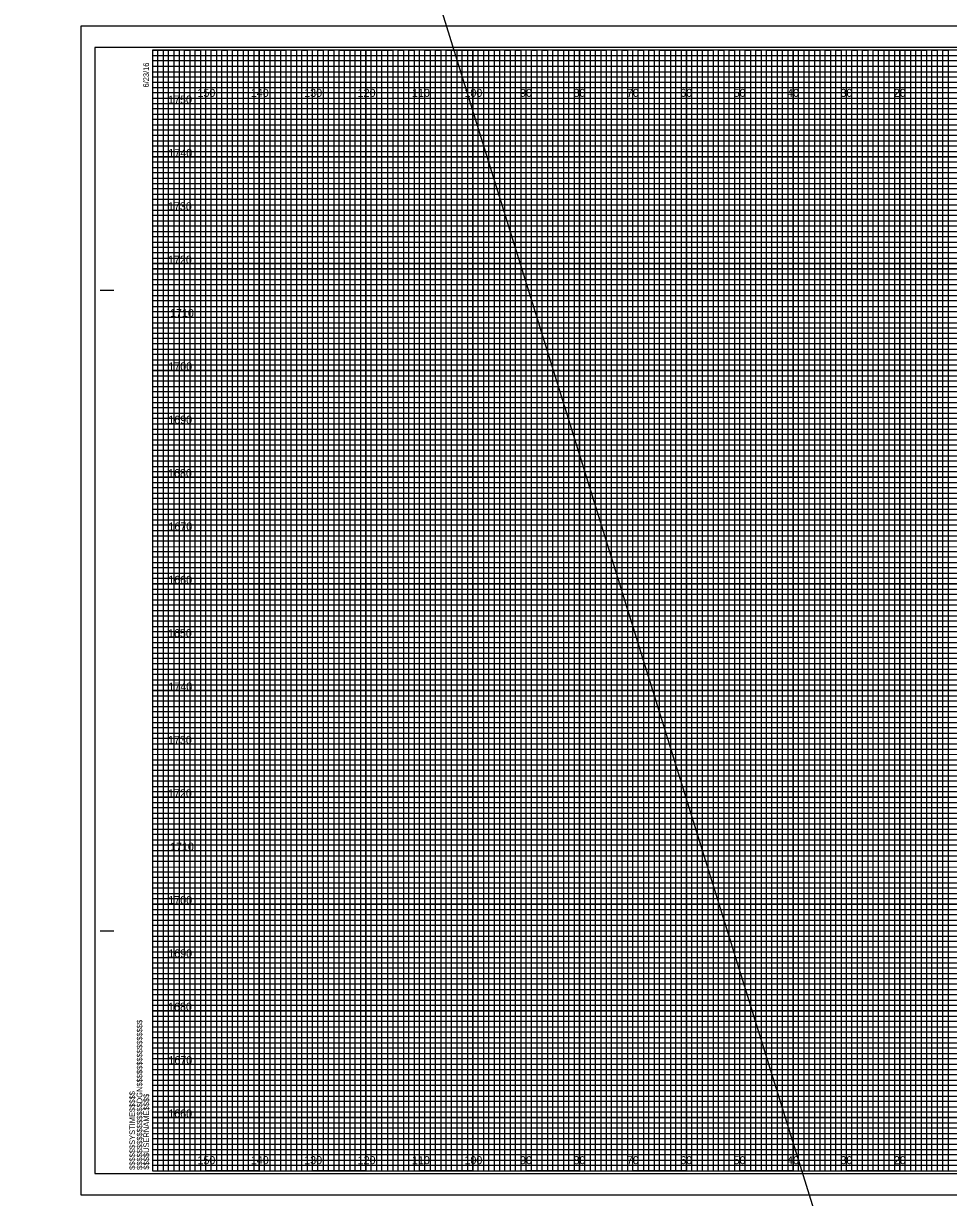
# Model space of a CAD drawing. Extents: x -419 to 4739, y -630 to 13534.
# Drawn here: x 1187.1 to 1360.3, y 859.1 to 1079.1 of the extents above; entities that cross this region are included whole.
import ezdxf

# ---------------------------------------------------------------- set-up
doc = ezdxf.new("R2010")
doc.units = 0
for name, color, linetype in [('Old_Level_62', 7, 'Continuous'), ('Pattern 1', 7, 'Continuous'), ('Pattern 18', 7, 'Continuous'), ('Pattern 4', 7, 'Continuous'), ('Pattern 5', 7, 'Continuous'), ('Prop Dimension', 7, 'Continuous'), ('Prop Horizontal Alignment', 7, 'Continuous'), ('Raster_Level_0', 7, 'Continuous'), ('Scratch_Level_0', 7, 'Continuous'), ('Scratch_Level_3', 7, 'Continuous'), ('Scratch_Level_5', 7, 'Continuous')]:
    doc.layers.add(name, color=color, linetype=linetype)

msp = doc.modelspace()

# ---------------------------------------------------------------- linework, layer by layer
at = {"layer": 'Old_Level_62'}
for p, q in [((1201.42, 1029.06), (1203.92, 1029.06)), ((1201.52, 1029.06), (1204.02, 1029.06)), ((1201.42, 909.06), (1203.92, 909.06)), ((1201.52, 909.06), (1204.02, 909.06)), ((1211.22, 864.06), (1211.22, 864.06)), ((1211.22, 864.06), (1211.22, 864.06)), ((1211.22, 864.06), (1211.22, 864.06)), ((1211.22, 864.06), (1211.22, 864.06)), ((1211.22, 864.06), (1211.22, 864.06)), ((1211.22, 864.06), (1211.22, 864.06)), ((1211.22, 864.06), (1211.22, 864.06))]:
    msp.add_line(p, q, dxfattribs=at)
msp.add_lwpolyline([(1531.22, 1074.06), (1211.22, 1074.06), (1211.22, 864.06), (1531.22, 864.06)], close=True, dxfattribs=at)
at = {"layer": 'Pattern 18'}
msp.add_line((-76.07, 5407.18), (1796.19, -630.13), dxfattribs=at)
msp.add_lwpolyline([(1197.82, 859.56), (1534.52, 859.56), (1534.52, 1078.56), (1197.82, 1078.56)], close=True, dxfattribs=at)
at = {"layer": 'Pattern 4'}
for p, q in [((1211.22, 1073.06), (1471.22, 1073.06)), ((1471.22, 1072.04), (1211.22, 1072.04)), ((1211.22, 1072.04), (1211.22, 1071.06)), ((1211.22, 1071.06), (1471.22, 1071.06)), ((1471.22, 1069.95), (1211.22, 1069.95)), ((1211.22, 1069.95), (1211.22, 1068.06)), ((1211.22, 1068.06), (1531.22, 1068.06))]:
    msp.add_line(p, q, dxfattribs=at)
for points in [[(1211.22, 1067.06), (1481.22, 1067.06), (1531.22, 1067.06), (1531.22, 1066.06), (1211.22, 1066.06)], [(1211.22, 1065.06), (1531.22, 1065.06), (1531.22, 1063.06), (1211.22, 1063.06)], [(1211.22, 1062.06), (1531.22, 1062.06), (1531.22, 1061.06), (1211.22, 1061.04)], [(1211.22, 1060.06), (1531.22, 1060.06), (1531.22, 1058.06), (1211.22, 1058.06)], [(1211.22, 1057.06), (1531.22, 1057.06), (1531.22, 1056.06), (1211.22, 1056.06)], [(1211.22, 1055.06), (1531.22, 1055.06), (1531.22, 1053.06), (1211.22, 1053.06)], [(1211.22, 1052.06), (1531.22, 1052.06), (1531.22, 1051.06), (1211.22, 1051.06)], [(1211.22, 1050.06), (1531.22, 1050.06), (1531.22, 1048.06), (1211.22, 1048.06)], [(1211.22, 1047.06), (1531.22, 1047.06), (1531.22, 1046.06), (1211.22, 1046.06)], [(1211.22, 1045.06), (1531.22, 1045.06), (1531.22, 1043.06), (1211.22, 1043.06)], [(1211.22, 1042.06), (1531.22, 1042.06), (1531.22, 1041.06), (1211.22, 1041.06)], [(1211.22, 1040.06), (1531.22, 1040.06), (1531.22, 1038.01), (1531.22, 1037.06), (1531.22, 1036.06), (1211.22, 1036.06)], [(1211.22, 1038.06), (1531.22, 1038.06), (1531.22, 1037.06), (1211.22, 1037.06)], [(1211.22, 1035.06), (1531.22, 1035.06), (1531.22, 1033.06), (1211.22, 1033.09)], [(1211.22, 1033.09), (1531.22, 1033.06), (1531.22, 1032.06), (1211.22, 1032.06)], [(1211.22, 1031.06), (1531.22, 1031.06), (1531.22, 1030.06), (1211.22, 1030.06)], [(1211.22, 1028.06), (1531.22, 1028.06), (1531.22, 1027.06), (1211.22, 1027.06)], [(1211.22, 1026.06), (1531.22, 1026.06), (1531.22, 1025.06), (1211.22, 1025.06)], [(1211.15, 1022.95), (1531.22, 1022.95), (1531.22, 1021.94), (1211.15, 1021.94)], [(1211.22, 1021.06), (1531.22, 1021.06), (1531.22, 1020.06), (1211.22, 1020.06)], [(1211.22, 1018.06), (1531.22, 1018.06), (1531.22, 1017.06), (1211.22, 1017.06)], [(1211.22, 1016.06), (1531.22, 1016.06), (1531.22, 1015.06), (1211.22, 1015.06)], [(1211.22, 1013.06), (1531.22, 1013.06), (1531.22, 1012.06), (1211.22, 1012.06)], [(1211.22, 1011.06), (1531.22, 1011.06), (1531.22, 1010.06), (1211.22, 1010.06)], [(1211.22, 1008.06), (1531.22, 1008.06), (1531.22, 1007.06), (1211.22, 1007.06)], [(1211.22, 1006.06), (1531.22, 1006.06), (1531.22, 1005.06), (1211.22, 1005.06)], [(1211.22, 1003.06), (1531.22, 1003.06), (1531.21, 1002.04), (1211.22, 1002.06)], [(1211.22, 1001.06), (1531.22, 1001.06), (1531.22, 1000.06), (1211.22, 1000.06)], [(1211.22, 998.06), (1531.22, 998.06), (1531.22, 997.06), (1211.22, 997.06)], [(1211.22, 996.06), (1531.22, 996.06), (1531.22, 995.06), (1211.22, 995.06)], [(1211.22, 993.06), (1531.22, 993.06), (1531.22, 992.06), (1211.22, 992.06)], [(1211.22, 991.06), (1531.22, 991.06), (1531.22, 990.06), (1211.22, 990.06)], [(1211.22, 988.06), (1531.22, 988.06), (1531.22, 987.06), (1211.22, 987.06)], [(1211.22, 986.06), (1531.22, 986.06), (1531.22, 985.06), (1211.22, 985.06)], [(1211.22, 983.06), (1531.22, 983.06), (1531.22, 982.06), (1211.22, 982.06)], [(1211.22, 981.05), (1531.29, 980.97), (1531.22, 980.06), (1211.22, 980.06)], [(1211.22, 978.06), (1531.22, 978.06), (1531.22, 977.06), (1211.22, 977.06)], [(1211.22, 976.06), (1531.22, 976.06), (1531.22, 975.06), (1211.22, 975.06)], [(1211.22, 973.06), (1531.22, 973.06), (1531.22, 972.06), (1211.22, 972.06)], [(1211.22, 971.06), (1531.22, 971.06), (1531.22, 970.06), (1211.22, 970.06)], [(1211.22, 968.06), (1531.22, 968.06), (1531.22, 967.06), (1211.22, 967.06)], [(1211.22, 966.06), (1531.22, 966.06), (1531.22, 965.06), (1211.22, 965.06)], [(1211.22, 963.06), (1531.22, 963.06), (1531.22, 962.06), (1211.22, 962.06)], [(1211.22, 961.06), (1531.22, 961.06), (1531.22, 960.06), (1211.22, 960.06)], [(1211.22, 958.06), (1531.22, 958.06), (1531.22, 957.06), (1211.22, 957.06)], [(1211.22, 956.06), (1531.22, 956.06), (1531.22, 955.06), (1211.22, 955.06)], [(1211.22, 953.06), (1531.22, 953.06), (1531.22, 952.06), (1211.22, 952.06)], [(1211.22, 951.06), (1531.22, 951.06), (1531.22, 950.06), (1211.22, 950.06)], [(1211.22, 948.06), (1531.22, 948.06), (1531.22, 947.06), (1211.22, 947.06)], [(1211.22, 946.06), (1531.22, 946.06), (1531.22, 945.06), (1211.22, 945.06)], [(1211.22, 943.06), (1531.22, 943.06), (1531.21, 942.04), (1211.22, 942.06)], [(1211.22, 941.06), (1531.22, 941.06), (1531.22, 940.06), (1211.22, 940.06)], [(1211.22, 938.06), (1531.22, 938.06), (1531.22, 937.06), (1211.22, 937.06)], [(1211.22, 936.06), (1531.22, 936.06), (1531.22, 935.06), (1211.22, 935.06)], [(1211.22, 933.06), (1531.22, 933.06), (1531.22, 932.06), (1211.22, 932.06)], [(1211.22, 931.06), (1531.22, 931.06), (1531.22, 930.06), (1211.22, 930.06)], [(1211.22, 928.06), (1531.22, 928.06), (1531.22, 927.06), (1211.22, 927.06)], [(1211.22, 926.06), (1531.22, 926.06), (1531.22, 925.06), (1211.22, 925.06)], [(1211.22, 923.06), (1531.22, 923.06), (1531.22, 922.06), (1211.22, 922.06)], [(1211.22, 921.05), (1531.29, 920.97), (1531.22, 920.06), (1211.22, 920.06)], [(1211.22, 918.06), (1531.22, 918.06), (1531.22, 917.06), (1211.22, 917.06)], [(1211.22, 916.06), (1531.22, 916.06), (1531.22, 915.06), (1211.22, 915.06)], [(1211.22, 913.06), (1531.22, 913.06), (1531.22, 912.06), (1211.22, 912.06)], [(1211.22, 911.06), (1531.22, 911.06), (1531.22, 910.06), (1211.22, 910.06)], [(1211.22, 908.06), (1531.22, 908.06), (1531.22, 907.06), (1211.22, 907.06)], [(1211.22, 906.06), (1531.22, 906.06), (1531.22, 905.06), (1211.22, 905.06)], [(1211.22, 903.06), (1531.22, 903.06), (1531.22, 902.06), (1211.22, 902.06)], [(1211.22, 901.06), (1531.22, 901.06), (1531.22, 900.06), (1211.22, 900.06)], [(1211.22, 898.06), (1531.22, 898.06), (1531.22, 897.06), (1211.22, 897.06)], [(1211.22, 896.06), (1531.22, 896.06), (1531.22, 895.06), (1211.22, 895.06)], [(1211.22, 893.06), (1531.22, 893.06), (1531.22, 892.06), (1211.22, 892.06)], [(1211.22, 891.06), (1531.22, 891.06), (1531.22, 890.06), (1211.22, 890.06)], [(1211.22, 888.06), (1531.22, 888.06), (1531.22, 887.06), (1211.22, 887.06)], [(1211.22, 886.06), (1531.22, 886.06), (1531.22, 885.06), (1211.22, 885.06)], [(1211.22, 883.06), (1531.22, 883.06), (1531.22, 882.06), (1211.22, 882.06)], [(1211.22, 881.06), (1531.22, 881.06), (1531.22, 880.06), (1211.22, 880.06)], [(1211.22, 878.06), (1531.22, 878.06), (1531.22, 877.06), (1211.22, 877.06)], [(1211.22, 876.06), (1531.22, 876.06), (1531.22, 875.06), (1211.22, 875.06)], [(1211.22, 873.06), (1531.22, 873.06), (1531.22, 872.06), (1211.22, 872.06)], [(1211.22, 871.06), (1531.22, 871.06), (1531.22, 870.06), (1211.22, 870.06)], [(1211.22, 868.06), (1531.22, 868.06), (1531.22, 867.06), (1211.22, 867.06)], [(1211.22, 866.06), (1531.22, 866.06), (1531.22, 865.06), (1211.22, 865.06)]]:
    msp.add_lwpolyline(points, dxfattribs=at)
at = {"layer": 'Pattern 5'}
for p, q in [((1534.52, 1078.56), (1197.82, 1078.56)), ((1197.82, 1078.56), (1197.82, 859.56)), ((1197.82, 859.56), (1534.52, 859.56))]:
    msp.add_line(p, q, dxfattribs=at)
at = {"layer": 'Prop Dimension'}
for points in [[(1211.22, 864.06), (1212.22, 864.06), (1212.22, 1074.06), (1213.22, 1074.06), (1213.22, 864.06)], [(1213.22, 864.06), (1214.22, 864.06), (1214.22, 1074.06), (1215.22, 1074.06), (1215.22, 864.06)], [(1216.22, 864.06), (1217.22, 864.06), (1217.22, 1074.06), (1218.22, 1074.06), (1218.22, 864.06)], [(1218.22, 864.06), (1219.22, 864.06), (1219.22, 1074.06), (1220.22, 1074.06), (1220.22, 864.06)], [(1221.22, 864.06), (1222.22, 864.06), (1222.22, 1074.06), (1223.22, 1074.06), (1223.22, 864.06)], [(1223.22, 864.06), (1224.22, 864.06), (1224.22, 1074.06), (1225.22, 1074.06), (1225.22, 864.06)], [(1226.22, 864.06), (1227.22, 864.06), (1227.22, 1074.06), (1228.22, 1074.06), (1228.22, 864.06)], [(1228.22, 864.06), (1229.22, 864.06), (1229.22, 1074.06), (1230.22, 1074.06), (1230.22, 864.06)], [(1231.22, 864.06), (1232.22, 864.06), (1232.22, 1074.06), (1233.22, 1074.06), (1233.22, 864.06)], [(1233.22, 864.06), (1234.22, 864.06), (1234.22, 1074.06), (1235.22, 1074.06), (1235.22, 864.06)], [(1236.22, 864.06), (1237.22, 864.06), (1237.22, 1074.06), (1238.22, 1074.06), (1238.22, 864.06)], [(1238.22, 864.06), (1239.22, 864.06), (1239.22, 1074.06), (1240.22, 1074.06), (1240.22, 864.06)], [(1241.22, 864.06), (1242.22, 864.06), (1242.22, 1074.06), (1243.22, 1074.06), (1243.22, 864.06)], [(1243.22, 864.06), (1244.22, 864.06), (1244.22, 1074.06), (1245.22, 1074.06), (1245.22, 864.06)], [(1246.22, 864.06), (1247.22, 864.06), (1247.22, 1074.06), (1248.22, 1074.06), (1248.22, 864.06)], [(1248.22, 864.06), (1249.22, 864.06), (1249.22, 1074.06), (1250.22, 1074.06), (1250.22, 864.06)], [(1251.22, 864.06), (1252.22, 864.06), (1252.22, 1074.06), (1253.22, 1074.06), (1253.22, 864.06)], [(1253.22, 864.06), (1254.22, 864.06), (1254.22, 1074.06), (1255.22, 1074.06), (1255.22, 864.06)], [(1256.22, 864.06), (1257.22, 864.06), (1257.22, 1074.06), (1258.22, 1074.06), (1258.22, 864.06)], [(1258.22, 864.06), (1259.22, 864.06), (1259.22, 1074.06), (1260.22, 1074.06), (1260.22, 864.06)], [(1261.22, 864.06), (1262.22, 864.06), (1262.22, 1074.06), (1263.22, 1074.06), (1263.22, 864.06)], [(1263.22, 864.06), (1264.22, 864.06), (1264.22, 1074.06), (1265.22, 1074.06), (1265.22, 864.06)], [(1266.22, 864.06), (1267.22, 864.06), (1267.22, 1074.06), (1268.22, 1074.06), (1268.22, 864.06)], [(1268.22, 864.06), (1269.22, 864.06), (1269.22, 1074.06), (1270.22, 1074.06), (1270.22, 864.06)], [(1271.22, 864.06), (1272.22, 864.06), (1272.22, 1074.06), (1273.22, 1074.06), (1273.22, 864.06)], [(1273.22, 864.06), (1274.22, 864.06), (1274.22, 1074.06), (1275.22, 1074.06), (1275.22, 864.06)], [(1276.22, 864.06), (1277.22, 864.06), (1277.22, 1074.06), (1278.22, 1074.06), (1278.22, 864.06)], [(1278.22, 864.06), (1279.22, 864.06), (1279.22, 1074.06), (1280.22, 1074.06), (1280.22, 864.06)], [(1281.22, 864.06), (1282.22, 864.06), (1282.22, 1074.06), (1283.22, 1074.06), (1283.22, 864.06)], [(1283.22, 864.06), (1284.22, 864.06), (1284.22, 1074.06), (1285.22, 1074.06), (1285.22, 864.06)], [(1286.22, 864.06), (1287.22, 864.06), (1287.22, 1074.06), (1288.22, 1074.06), (1288.22, 864.06)], [(1288.22, 864.06), (1289.22, 864.06), (1289.22, 1074.06), (1290.22, 1074.06), (1290.22, 864.06)], [(1291.22, 864.06), (1292.22, 864.06), (1292.22, 1074.06), (1293.22, 1074.06), (1293.22, 864.06)], [(1293.22, 864.06), (1294.22, 864.06), (1294.22, 1074.06), (1295.22, 1074.06), (1295.22, 864.06)], [(1296.22, 864.06), (1297.22, 864.06), (1297.22, 1074.06), (1298.22, 1074.06), (1298.22, 864.06)], [(1298.22, 864.06), (1299.22, 864.06), (1299.22, 1074.06), (1300.22, 1074.06), (1300.22, 864.06)], [(1301.22, 864.06), (1302.22, 864.06), (1302.22, 1074.06), (1303.22, 1074.06), (1303.22, 864.06)], [(1303.22, 864.06), (1304.22, 864.06), (1304.22, 1074.06), (1305.22, 1074.06), (1305.22, 864.06)], [(1306.22, 864.06), (1307.22, 864.06), (1307.22, 1074.06), (1308.22, 1074.06), (1308.22, 864.06)], [(1308.22, 864.06), (1309.22, 864.06), (1309.22, 1074.06), (1310.22, 1074.06), (1310.22, 864.06)], [(1311.22, 864.06), (1312.22, 864.06), (1312.22, 1074.06), (1313.22, 1074.06), (1313.22, 864.06)], [(1313.22, 864.06), (1314.22, 864.06), (1314.22, 1074.06), (1315.22, 1074.06), (1315.22, 864.06)], [(1316.22, 864.06), (1317.22, 864.06), (1317.22, 1074.06), (1318.22, 1074.06), (1318.22, 864.06)], [(1318.22, 864.06), (1319.22, 864.06), (1319.22, 1074.06), (1320.22, 1074.06), (1320.22, 864.06)], [(1321.22, 864.06), (1322.22, 864.06), (1322.22, 1074.06), (1323.22, 1074.06), (1323.22, 864.06)], [(1323.22, 864.06), (1324.22, 864.06), (1324.22, 1074.06), (1325.22, 1074.06), (1325.22, 864.06)], [(1326.22, 864.06), (1327.22, 864.06), (1327.22, 1074.06), (1328.22, 1074.06), (1328.22, 864.06)], [(1328.22, 864.06), (1329.22, 864.06), (1329.22, 1074.06), (1330.22, 1074.06), (1330.22, 864.06)], [(1331.22, 864.06), (1332.22, 864.06), (1332.22, 1074.06), (1333.22, 1074.06), (1333.22, 864.06)], [(1333.22, 864.06), (1334.22, 864.06), (1334.22, 1074.06), (1335.22, 1074.06), (1335.22, 864.06)], [(1336.22, 864.06), (1337.22, 864.06), (1337.22, 1074.06), (1338.22, 1074.06), (1338.22, 864.06)], [(1338.22, 864.06), (1339.22, 864.06), (1339.22, 1074.06), (1340.22, 1074.06), (1340.22, 864.06)], [(1341.22, 864.06), (1342.22, 864.06), (1342.22, 1074.06), (1343.22, 1074.06), (1343.22, 864.06)], [(1343.22, 864.06), (1344.22, 864.06), (1344.22, 1074.06), (1345.22, 1074.06), (1345.22, 864.06)], [(1346.22, 864.06), (1347.22, 864.06), (1347.22, 1074.06), (1348.22, 1074.06), (1348.22, 864.06)], [(1348.22, 864.06), (1349.22, 864.06), (1349.22, 1074.06), (1350.22, 1074.06), (1350.22, 864.06)], [(1351.22, 864.06), (1352.22, 864.06), (1352.22, 1074.06), (1353.22, 1074.06), (1353.22, 864.06)], [(1353.22, 864.06), (1354.22, 864.06), (1354.22, 1074.06), (1355.22, 1074.06), (1355.22, 864.06)], [(1356.22, 864.06), (1357.22, 864.06), (1357.22, 1074.06), (1358.22, 1074.06), (1358.22, 864.06)], [(1358.22, 864.06), (1359.22, 864.06), (1359.22, 1074.06), (1360.22, 1074.06), (1360.22, 864.06)]]:
    msp.add_lwpolyline(points, dxfattribs=at)
at = {"layer": 'Prop Horizontal Alignment'}
for points in [[(1211.22, 1074.06), (1216.22, 1074.06), (1216.22, 864.06), (1226.22, 864.06), (1226.22, 1074.06), (1236.22, 1074.06), (1236.22, 864.06), (1246.22, 864.06), (1246.22, 1074.06), (1256.22, 1074.06), (1256.22, 864.06), (1266.22, 864.06), (1266.22, 1074.06), (1276.22, 1074.06), (1276.22, 864.06), (1286.22, 864.06), (1286.22, 1074.06), (1296.22, 1074.06), (1296.22, 864.06), (1306.22, 864.06), (1306.22, 1074.06), (1316.22, 1074.06), (1316.22, 864.06), (1326.22, 864.06), (1326.22, 1074.06), (1336.22, 1074.06), (1336.22, 864.06), (1346.22, 864.06), (1346.22, 1074.06), (1356.22, 1074.06), (1356.22, 864.06), (1366.22, 864.06)], [(1211.22, 1069.06), (1486.22, 1069.06)], [(1211.22, 1049.06), (1531.22, 1049.06), (1531.22, 1059.06), (1211.22, 1059.06)], [(1211.22, 1029.06), (1531.22, 1029.06), (1531.22, 1039.06), (1211.22, 1039.06)], [(1211.22, 1009.06), (1531.22, 1009.06), (1531.22, 1019.06), (1211.22, 1019.06)], [(1211.22, 989.06), (1531.22, 989.06), (1531.22, 999.06), (1211.22, 999.06)], [(1211.22, 969.06), (1531.22, 969.06), (1531.22, 979.06), (1211.22, 979.06)], [(1211.22, 949.06), (1531.22, 949.06), (1531.22, 959.06), (1211.22, 959.06)], [(1211.22, 929.06), (1531.22, 929.06), (1531.22, 939.06), (1211.22, 939.06)], [(1211.22, 909.06), (1531.22, 909.06), (1531.22, 919.06), (1211.22, 919.06)], [(1211.22, 889.06), (1531.22, 889.06), (1531.22, 899.06), (1211.22, 899.06)], [(1211.22, 869.06), (1531.22, 869.06), (1531.22, 879.06), (1211.22, 879.06)]]:
    msp.add_lwpolyline(points, dxfattribs=at)
at = {"layer": 'Scratch_Level_0'}
for p, q in [((1221.22, 864.06), (1221.22, 1074.06)), ((1231.22, 864.06), (1231.22, 1074.06)), ((1241.22, 864.06), (1241.22, 1074.06)), ((1251.22, 864.06), (1251.22, 1074.06)), ((1261.22, 864.06), (1261.22, 1074.06)), ((1271.22, 864.06), (1271.22, 1074.06)), ((1281.22, 864.06), (1281.22, 1074.06)), ((1291.22, 864.06), (1291.22, 1074.06)), ((1301.22, 864.06), (1301.22, 1074.06)), ((1311.22, 864.06), (1311.22, 1074.06)), ((1321.22, 864.06), (1321.22, 1074.06)), ((1331.22, 864.06), (1331.22, 1074.06)), ((1341.22, 864.06), (1341.22, 1074.06)), ((1351.22, 864.06), (1351.22, 1074.06)), ((1211.22, 1064.06), (1531.22, 1064.06)), ((1211.22, 1054.06), (1531.22, 1054.06)), ((1211.22, 1044.06), (1531.22, 1044.06)), ((1211.22, 1034.06), (1531.22, 1034.06)), ((1211.22, 1024.06), (1531.22, 1024.06)), ((1211.22, 1014.06), (1531.22, 1014.06)), ((1211.22, 1004.06), (1531.22, 1004.06)), ((1211.22, 994.06), (1531.22, 994.06)), ((1211.22, 984.06), (1531.22, 984.06)), ((1211.22, 974.06), (1531.22, 974.06)), ((1211.22, 964.06), (1531.22, 964.06)), ((1211.22, 954.06), (1531.22, 954.06)), ((1211.22, 944.06), (1531.22, 944.06)), ((1211.22, 934.06), (1531.22, 934.06)), ((1211.22, 924.06), (1531.22, 924.06)), ((1211.22, 914.06), (1531.22, 914.06)), ((1211.22, 904.06), (1531.22, 904.06)), ((1211.22, 894.06), (1531.22, 894.06)), ((1211.22, 884.06), (1531.22, 884.06)), ((1211.22, 874.06), (1531.22, 874.06))]:
    msp.add_line(p, q, dxfattribs=at)
at = {"layer": 'Scratch_Level_3'}
for p, q in [((1221.22, 1074.06), (1211.22, 1074.06)), ((1221.22, 864.06), (1221.22, 1074.06)), ((1241.22, 1074.06), (1231.22, 1074.06)), ((1231.22, 1074.06), (1231.22, 864.06)), ((1241.22, 864.06), (1241.22, 1074.06)), ((1261.22, 1074.06), (1251.22, 1074.06)), ((1251.22, 1074.06), (1251.22, 864.06)), ((1261.22, 864.06), (1261.22, 1074.06)), ((1281.22, 1074.06), (1271.22, 1074.06)), ((1271.22, 1074.06), (1271.22, 864.06)), ((1281.22, 864.06), (1281.22, 1074.06)), ((1301.22, 1074.06), (1291.22, 1074.06)), ((1291.22, 1074.06), (1291.22, 864.06)), ((1301.22, 864.06), (1301.22, 1074.06)), ((1321.22, 1074.06), (1311.22, 1074.06)), ((1311.22, 1074.06), (1311.22, 864.06)), ((1321.22, 864.06), (1321.22, 1074.06)), ((1341.22, 1074.06), (1331.22, 1074.06)), ((1331.22, 1074.06), (1331.22, 864.06)), ((1341.22, 864.06), (1341.22, 1074.06)), ((1361.22, 1074.06), (1351.22, 1074.06)), ((1351.22, 1074.06), (1351.22, 864.06)), ((1231.22, 864.06), (1221.22, 864.06)), ((1251.22, 864.06), (1241.22, 864.06)), ((1271.22, 864.06), (1261.22, 864.06)), ((1291.22, 864.06), (1281.22, 864.06)), ((1311.22, 864.06), (1301.22, 864.06)), ((1331.22, 864.06), (1321.22, 864.06)), ((1351.22, 864.06), (1341.22, 864.06))]:
    msp.add_line(p, q, dxfattribs=at)
for points in [[(1211.22, 1064.06), (1531.22, 1064.06), (1531.22, 1054.06), (1211.22, 1054.06)], [(1211.22, 1044.06), (1531.22, 1044.06), (1531.22, 1034.06), (1211.22, 1034.06)], [(1211.22, 1024.06), (1531.22, 1024.06), (1531.22, 1014.06), (1211.22, 1014.06)], [(1211.22, 1004.06), (1531.22, 1004.06), (1531.22, 994.06), (1211.22, 994.06)], [(1211.22, 984.06), (1531.22, 984.06), (1531.22, 974.06), (1211.22, 974.06)], [(1211.22, 964.06), (1531.22, 964.06), (1531.22, 954.06), (1211.22, 954.06)], [(1211.22, 944.06), (1531.22, 944.06), (1531.22, 934.06), (1211.22, 934.06)], [(1211.22, 924.06), (1531.22, 924.06), (1531.22, 914.06), (1211.22, 914.06)], [(1211.22, 904.06), (1531.22, 904.06), (1531.22, 894.06), (1211.22, 894.06)], [(1211.22, 884.06), (1531.22, 884.06), (1531.22, 874.06), (1211.22, 874.06)]]:
    msp.add_lwpolyline(points, dxfattribs=at)
at = {"layer": 'Scratch_Level_5'}
msp.add_lwpolyline([(1200.42, 863.56), (1533.62, 863.56), (1533.62, 1074.56), (1200.42, 1074.56)], close=True, dxfattribs=at)

# ---------------------------------------------------------------- texts
at = {"layer": 'Old_Level_62'}
for s, p in [('6/23/16', (1210.57, 1067.06)), ('$$$$$$$$$$$$$$$$DGN$$$$$$$$$$$$$$$$', (1209.34, 864.24)), ('$$$$$$SYSTIME$$$$$', (1207.96, 864.24)), ('$$$$USERNAME$$$$', (1210.6, 864.29))]:
    msp.add_text(s, height=1.05, rotation=90, dxfattribs=at).set_placement(p)
at = {"layer": 'Pattern 1'}
for s, p in [('1750', (1214.17, 1064.06)), ('1740', (1214.22, 1054.06)), ('1730', (1214.14, 1044.06)), ('1720', (1214.15, 1034.06)), ('1710', (1214.53, 1024.06)), ('1700', (1214.2, 1014.06)), ('1690', (1214.19, 1004.06)), ('1680', (1214.16, 994.06)), ('1670', (1214.22, 984.06)), ('1660', (1214.19, 974.06)), ('1650', (1214.14, 964.06)), ('1740', (1214.22, 954.06)), ('1730', (1214.14, 944.06)), ('1720', (1214.15, 934.06)), ('1710', (1214.53, 924.06)), ('1700', (1214.2, 914.06)), ('1690', (1214.19, 904.06)), ('1680', (1214.16, 894.06)), ('1670', (1214.22, 884.06)), ('1660', (1214.19, 874.06))]:
    msp.add_text(s, height=1.5, dxfattribs=at).set_placement(p)
at = {"layer": 'Raster_Level_0'}
for s, p in [('150', (1219.66, 1065.31)), ('140', (1229.66, 1065.31)), ('130', (1239.66, 1065.31)), ('120', (1249.66, 1065.31)), ('110', (1259.84, 1065.31)), ('100', (1269.66, 1065.31)), ('90', (1280.08, 1065.31)), ('80', (1290.08, 1065.31)), ('70', (1300.08, 1065.31)), ('60', (1310.08, 1065.31)), ('50', (1320.08, 1065.31)), ('40', (1330.08, 1065.31)), ('30', (1340.08, 1065.31)), ('20', (1350.08, 1065.31)), ('150', (1219.66, 865.31)), ('140', (1229.66, 865.31)), ('130', (1239.66, 865.31)), ('120', (1249.66, 865.31)), ('110', (1259.84, 865.31)), ('100', (1269.66, 865.31)), ('90', (1280.08, 865.31)), ('80', (1290.08, 865.31)), ('70', (1300.08, 865.31)), ('60', (1310.08, 865.31)), ('50', (1320.08, 865.31)), ('40', (1330.08, 865.31)), ('30', (1340.08, 865.31)), ('20', (1350.08, 865.31))]:
    msp.add_text(s, height=1.5, dxfattribs=at).set_placement(p)

doc.saveas('drawing.dxf')
